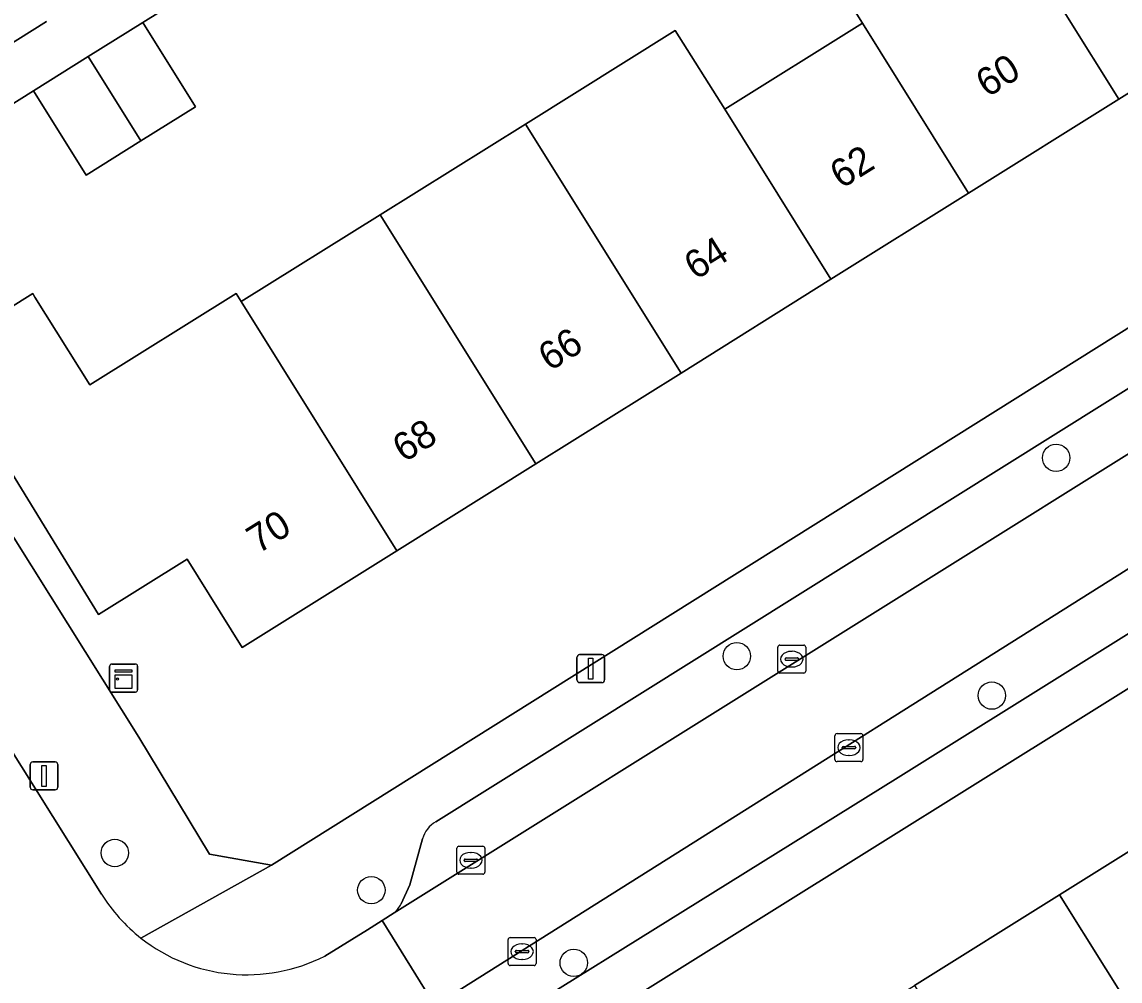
# Model space of a CAD drawing. Extents: x 159352 to 160617, y 385888 to 387323.
# Drawn here: x 159671.45 to 159710.67, y 386048.83 to 386083.08 of the extents above; entities that cross this region are included whole.
import ezdxf

# ---------------------------------------------------------------- set-up
doc = ezdxf.new("R2010")
doc.units = 0
for name, color, linetype in [('IMGEO_Boom', 7, 'Continuous'), ('IMGEO_Erf', 7, 'Continuous'), ('IMGEO_Kast', 7, 'Continuous'), ('IMGEO_Kolk', 7, 'Continuous'), ('IMGEO_Lichtmast', 7, 'Continuous'), ('IMGEO_Pand', 7, 'Continuous'), ('IMGEO_Pand_nummerreeks', 7, 'Continuous'), ('IMGEO_Parkeervlak_open', 7, 'Continuous'), ('IMGEO_Rijbaan_lokaal_open', 7, 'Continuous'), ('IMGEO_Voetpad_gesloten', 7, 'Continuous'), ('IMGEO_Voetpad_open', 7, 'Continuous')]:
    doc.layers.add(name, color=color, linetype=linetype)

msp = doc.modelspace()

# ---------------------------------------------------------------- linework, layer by layer
at = {"layer": 'IMGEO_Boom'}
for centre in [(159708.383, 386067.514), (159696.983, 386060.434), (159706.089, 386059.024), (159674.766, 386053.404), (159683.927, 386052.079), (159691.156, 386049.481)]:
    msp.add_circle(centre, 0.489, dxfattribs=at)
at = {"layer": 'IMGEO_Erf'}
for points in [[(159627.21, 386134.74), (159663.189, 386077.37), (159672.327, 386083.101)], [(159682.021, 386086.971), (159675.765, 386083.062), (159677.645, 386080.051), (159675.693, 386078.833), (159673.743, 386077.616), (159671.864, 386080.628), (159664.171, 386075.803), (159675.622, 386057.544), (159678.147, 386053.368), (159680.364, 386052.973), (159727.06, 386082.254), (159727.834, 386084.857)], [(159715.741, 386083.528), (159710.62, 386080.324), (159705.257, 386076.97), (159700.341, 386073.894), (159694.987, 386070.545), (159689.802, 386067.302), (159684.835, 386064.194), (159679.316, 386060.742), (159677.344, 386063.895), (159674.183, 386061.917), (159668.443, 386071.26), (159671.836, 386073.379), (159671.913, 386073.256), (159673.873, 386070.118), (159679.098, 386073.381), (159679.277, 386073.094), (159684.247, 386076.198), (159689.434, 386079.437), (159694.775, 386082.772), (159696.55, 386079.963), (159701.469, 386083.035), (159701.464, 386083.043), (159699.747, 386085.796)], [(159692.572, 386024.604), (159688.668, 386030.843), (159686.251, 386029.331), (159682.354, 386035.559), (159687.801, 386038.964), (159692.982, 386042.203), (159698.161, 386045.441), (159703.328, 386048.671), (159708.502, 386051.905), (159713.682, 386055.143)]]:
    msp.add_lwpolyline(points, dxfattribs=at)
msp.add_lwpolyline([(159733.186, 386035.211), (159730.405, 386039.383), (159739.998, 386045.377), (159726.053, 386067.427), (159724.652, 386067.823), (159682.76, 386041.661), (159677.195, 386038.177), (159676.499, 386035.726), (159692.861, 386009.756), (159693.588, 386010.224), (159695.905, 386011.714), (159692.99, 386016.431), (159699.422, 386020.406), (159702.337, 386015.688), (159707.722, 386019.015), (159705.988, 386021.823), (159710.701, 386024.734), (159712.435, 386021.927)], close=True, dxfattribs=at)
at = {"layer": 'IMGEO_Kast'}
for p, q in [((159674.58, 386059.227), (159674.58, 386060.068)), ((159674.58, 386060.068), (159674.58, 386059.227)), ((159674.655, 386060.152), (159675.496, 386060.152)), ((159675.496, 386060.152), (159674.655, 386060.152)), ((159675.58, 386060.077), (159675.58, 386059.236)), ((159675.58, 386059.236), (159675.58, 386060.077)), ((159675.505, 386059.152), (159674.664, 386059.152)), ((159674.664, 386059.152), (159675.505, 386059.152))]:
    msp.add_line(p, q, dxfattribs=at)
for points in [[(159674.775, 386059.942), (159675.375, 386059.942), (159675.375, 386059.857), (159674.775, 386059.857), (159674.775, 386059.942)], [(159674.775, 386059.767), (159675.375, 386059.767), (159675.375, 386059.278), (159674.775, 386059.278), (159674.775, 386059.767)]]:
    msp.add_lwpolyline(points, dxfattribs=at)
msp.add_circle((159674.859, 386059.616), 0.0377, dxfattribs=at)
for centre, start, end in [((159674.658, 386060.074), 92.4484, 184.2845), ((159674.658, 386060.074), 92.4484, 184.2845), ((159675.502, 386060.074), 2.4484, 94.2845), ((159675.502, 386060.074), 2.4484, 94.2845), ((159674.658, 386059.23), 182.4484, 274.2845), ((159674.658, 386059.23), 182.4484, 274.2845), ((159675.502, 386059.23), 272.4484, 4.2845), ((159675.502, 386059.23), 272.4484, 4.2845)]:
    msp.add_arc(centre, 0.0779, start, end, dxfattribs=at)
at = {"layer": 'IMGEO_Kolk'}
for p, q in [((159698.443, 386059.9), (159698.443, 386060.752)), ((159698.518, 386060.826), (159699.37, 386060.826)), ((159698.931, 386060.606), (159698.956, 386060.606)), ((159699.444, 386060.752), (159699.444, 386059.9)), ((159698.702, 386060.32), (159698.702, 386060.332)), ((159699.14, 386060.283), (159698.742, 386060.283)), ((159698.745, 386060.369), (159699.143, 386060.369)), ((159699.186, 386060.332), (159699.186, 386060.32)), ((159699.37, 386059.826), (159698.518, 386059.826)), ((159698.954, 386060.046), (159698.929, 386060.046)), ((159700.484, 386056.741), (159700.484, 386057.593)), ((159700.559, 386057.667), (159701.411, 386057.667)), ((159700.972, 386057.447), (159700.997, 386057.447)), ((159701.485, 386057.593), (159701.485, 386056.741)), ((159700.743, 386057.161), (159700.743, 386057.173)), ((159701.181, 386057.124), (159700.783, 386057.124)), ((159700.786, 386057.21), (159701.184, 386057.21)), ((159701.227, 386057.173), (159701.227, 386057.161)), ((159701.411, 386056.667), (159700.559, 386056.667)), ((159700.995, 386056.887), (159700.97, 386056.887)), ((159686.982, 386052.719), (159686.982, 386053.571)), ((159687.057, 386053.645), (159687.909, 386053.645)), ((159687.983, 386053.571), (159687.983, 386052.719)), ((159687.241, 386053.139), (159687.241, 386053.151)), ((159687.284, 386053.188), (159687.682, 386053.188)), ((159687.47, 386053.425), (159687.495, 386053.425)), ((159687.725, 386053.151), (159687.725, 386053.139)), ((159687.679, 386053.102), (159687.281, 386053.102)), ((159687.493, 386052.865), (159687.468, 386052.865)), ((159687.909, 386052.645), (159687.057, 386052.645)), ((159688.886, 386050.383), (159689.738, 386050.383)), ((159688.811, 386049.457), (159688.811, 386050.309)), ((159689.299, 386050.163), (159689.324, 386050.163)), ((159689.812, 386050.309), (159689.812, 386049.457)), ((159689.07, 386049.877), (159689.07, 386049.889)), ((159689.508, 386049.84), (159689.11, 386049.84)), ((159689.113, 386049.926), (159689.511, 386049.926)), ((159689.322, 386049.603), (159689.297, 386049.603)), ((159689.554, 386049.889), (159689.554, 386049.877)), ((159689.738, 386049.383), (159688.886, 386049.383))]:
    msp.add_line(p, q, dxfattribs=at)
for points in [[(159698.443, 386059.9), (159698.443, 386060.752)], [(159698.518, 386060.826), (159699.37, 386060.826)], [(159699.444, 386060.752), (159699.444, 386059.9)], [(159699.37, 386059.826), (159698.518, 386059.826)], [(159700.484, 386056.741), (159700.484, 386057.593)], [(159700.559, 386057.667), (159701.411, 386057.667)], [(159701.485, 386057.593), (159701.485, 386056.741)], [(159701.411, 386056.667), (159700.559, 386056.667)], [(159686.982, 386052.719), (159686.982, 386053.571)], [(159687.057, 386053.645), (159687.909, 386053.645)], [(159687.983, 386053.571), (159687.983, 386052.719)], [(159687.909, 386052.645), (159687.057, 386052.645)], [(159688.886, 386050.383), (159689.738, 386050.383)], [(159688.811, 386049.457), (159688.811, 386050.309)], [(159689.812, 386050.309), (159689.812, 386049.457)], [(159689.738, 386049.383), (159688.886, 386049.383)]]:
    msp.add_lwpolyline(points, dxfattribs=at)
for centre, radius, start, end in [((159698.52, 386060.75), 0.0765, 91.552, 178.448), ((159698.52, 386060.75), 0.0765, 91.552, 178.448), ((159699.368, 386060.75), 0.0765, 1.552, 88.448), ((159699.368, 386060.75), 0.0765, 1.552, 88.448), ((159698.742, 386060.329), 0.0403, 85.8775, 175.7526), ((159698.739, 386060.319), 0.0366, 178.938, 274.7102), ((159699.143, 386060.326), 0.043, 264.8664, 352.4533), ((159699.147, 386060.331), 0.0386, 1.7309, 96.639), ((159698.52, 386059.902), 0.0765, 181.552, 268.448), ((159698.52, 386059.902), 0.0765, 181.552, 268.448), ((159699.368, 386059.902), 0.0765, 271.552, 358.448), ((159699.368, 386059.902), 0.0765, 271.552, 358.448), ((159700.561, 386057.591), 0.0765, 91.552, 178.448), ((159700.561, 386057.591), 0.0765, 91.552, 178.448), ((159701.409, 386057.591), 0.0765, 1.552, 88.448), ((159701.409, 386057.591), 0.0765, 1.552, 88.448), ((159700.783, 386057.17), 0.0403, 85.8775, 175.7526), ((159700.78, 386057.16), 0.0366, 178.938, 274.7102), ((159701.184, 386057.167), 0.043, 264.8664, 352.4533), ((159701.188, 386057.172), 0.0386, 1.7309, 96.639), ((159700.561, 386056.743), 0.0765, 181.552, 268.448), ((159700.561, 386056.743), 0.0765, 181.552, 268.448), ((159701.409, 386056.743), 0.0765, 271.552, 358.448), ((159701.409, 386056.743), 0.0765, 271.552, 358.448), ((159687.059, 386053.569), 0.0765, 91.552, 178.448), ((159687.059, 386053.569), 0.0765, 91.552, 178.448), ((159687.907, 386053.569), 0.0765, 1.552, 88.448), ((159687.907, 386053.569), 0.0765, 1.552, 88.448), ((159687.281, 386053.148), 0.0403, 85.8775, 175.7526), ((159687.278, 386053.138), 0.0366, 178.938, 274.7102), ((159687.682, 386053.145), 0.043, 264.8664, 352.4533), ((159687.686, 386053.15), 0.0386, 1.7309, 96.639), ((159687.059, 386052.721), 0.0765, 181.552, 268.448), ((159687.059, 386052.721), 0.0765, 181.552, 268.448), ((159687.907, 386052.721), 0.0765, 271.552, 358.448), ((159687.907, 386052.721), 0.0765, 271.552, 358.448), ((159688.888, 386050.307), 0.0765, 91.552, 178.448), ((159688.888, 386050.307), 0.0765, 91.552, 178.448), ((159689.736, 386050.307), 0.0765, 1.552, 88.448), ((159689.736, 386050.307), 0.0765, 1.552, 88.448), ((159689.11, 386049.886), 0.0403, 85.8775, 175.7526), ((159689.107, 386049.876), 0.0366, 178.938, 274.7102), ((159689.511, 386049.883), 0.043, 264.8664, 352.4533), ((159689.515, 386049.888), 0.0386, 1.7309, 96.639), ((159688.888, 386049.459), 0.0765, 181.552, 268.448), ((159688.888, 386049.459), 0.0765, 181.552, 268.448), ((159689.736, 386049.459), 0.0765, 271.552, 358.448), ((159689.736, 386049.459), 0.0765, 271.552, 358.448)]:
    msp.add_arc(centre, radius, start, end, dxfattribs=at)
for centre, major_axis, ratio, start_param, end_param in [((159698.93, 386060.326), (-0.387, 0.002), 0.722429, 4.712389, 7.853982), ((159698.955, 386060.326), (-0.39, 0.002), 0.717154, 1.570796, 4.712389), ((159700.971, 386057.167), (-0.387, 0.002), 0.722429, 4.712389, 7.853982), ((159700.996, 386057.167), (-0.39, 0.002), 0.717154, 1.570796, 4.712389), ((159687.469, 386053.145), (-0.387, 0.002), 0.722429, 4.712389, 7.853982), ((159687.494, 386053.145), (-0.39, 0.002), 0.717154, 1.570796, 4.712389), ((159689.298, 386049.883), (-0.387, 0.002), 0.722429, 4.712389, 7.853982), ((159689.323, 386049.883), (-0.39, 0.002), 0.717154, 1.570796, 4.712389)]:
    msp.add_ellipse(centre, major_axis=major_axis, ratio=ratio, start_param=start_param, end_param=end_param, dxfattribs=at)
at = {"layer": 'IMGEO_Lichtmast'}
for p, q in [((159691.267, 386059.587), (159691.267, 386060.387)), ((159691.267, 386060.387), (159691.267, 386059.587)), ((159691.367, 386060.487), (159692.157, 386060.487)), ((159692.157, 386060.487), (159691.367, 386060.487)), ((159692.257, 386060.387), (159692.257, 386059.587)), ((159692.257, 386059.587), (159692.257, 386060.387)), ((159692.157, 386059.487), (159691.367, 386059.487)), ((159691.367, 386059.487), (159692.157, 386059.487)), ((159671.842, 386056.659), (159672.632, 386056.659)), ((159672.632, 386056.659), (159671.842, 386056.659)), ((159671.742, 386055.759), (159671.742, 386056.559)), ((159671.742, 386056.559), (159671.742, 386055.759)), ((159672.732, 386056.559), (159672.732, 386055.759)), ((159672.732, 386055.759), (159672.732, 386056.559)), ((159672.632, 386055.659), (159671.842, 386055.659)), ((159671.842, 386055.659), (159672.632, 386055.659))]:
    msp.add_line(p, q, dxfattribs=at)
for points in [[(159691.687, 386060.362), (159691.837, 386060.362), (159691.837, 386059.612), (159691.687, 386059.612), (159691.687, 386060.362)], [(159672.162, 386056.534), (159672.312, 386056.534), (159672.312, 386055.784), (159672.162, 386055.784), (159672.162, 386056.534)]]:
    msp.add_lwpolyline(points, dxfattribs=at)
for centre, start, end in [((159691.367, 386060.387), 90, 180), ((159691.367, 386060.387), 90, 180), ((159692.157, 386060.387), 0, 90), ((159692.157, 386060.387), 360, 90), ((159691.367, 386059.587), 180, 270), ((159691.367, 386059.587), 180, 270), ((159692.157, 386059.587), 270, 0), ((159692.157, 386059.587), 270, 0), ((159671.842, 386056.559), 90, 180), ((159671.842, 386056.559), 90, 180), ((159672.632, 386056.559), 0, 90), ((159672.632, 386056.559), 360, 90), ((159671.842, 386055.759), 180, 270), ((159671.842, 386055.759), 180, 270), ((159672.632, 386055.759), 270, 0), ((159672.632, 386055.759), 270, 0)]:
    msp.add_arc(centre, 0.1, start, end, dxfattribs=at)
at = {"layer": 'IMGEO_Pand'}
for points in [[(159710.256, 386092.311), (159705.178, 386089.14), (159705.249, 386089.026), (159706.834, 386086.386), (159710.62, 386080.324), (159715.741, 386083.528)], [(159706.834, 386086.386), (159705.249, 386089.026), (159705.178, 386089.14), (159699.712, 386085.853), (159699.747, 386085.796), (159701.464, 386083.043), (159701.469, 386083.035), (159705.257, 386076.97), (159710.62, 386080.324)], [(159675.693, 386078.833), (159677.645, 386080.051), (159675.765, 386083.062), (159673.813, 386081.844)], [(159700.341, 386073.894), (159705.257, 386076.97), (159701.469, 386083.035), (159696.55, 386079.963)], [(159696.55, 386079.963), (159694.775, 386082.772), (159689.434, 386079.437), (159694.987, 386070.545), (159700.341, 386073.894)], [(159673.813, 386081.844), (159671.864, 386080.628), (159673.743, 386077.616), (159675.693, 386078.833)], [(159689.802, 386067.302), (159694.987, 386070.545), (159689.434, 386079.437), (159684.247, 386076.198)], [(159679.277, 386073.094), (159684.835, 386064.194), (159689.802, 386067.302), (159684.247, 386076.198)], [(159679.098, 386073.381), (159673.873, 386070.118), (159671.913, 386073.256), (159671.836, 386073.379), (159668.443, 386071.26), (159674.183, 386061.917), (159677.344, 386063.895), (159679.316, 386060.742), (159684.835, 386064.194), (159679.277, 386073.094)], [(159713.682, 386055.143), (159708.502, 386051.905), (159713.466, 386043.98), (159713.984, 386043.152), (159713.74, 386042.999), (159715.63, 386039.982), (159717.73, 386041.298), (159715.841, 386044.315), (159719.171, 386046.4)], [(159708.502, 386051.905), (159703.328, 386048.671), (159707.246, 386042.417), (159708.294, 386040.745), (159711.6, 386042.813), (159715.372, 386036.791), (159716.992, 386037.806), (159715.63, 386039.982), (159713.74, 386042.999), (159713.984, 386043.152), (159713.466, 386043.98)]]:
    msp.add_lwpolyline(points, close=True, dxfattribs=at)
at = {"layer": 'IMGEO_Parkeervlak_open'}
for points in [[(159684.747, 386051.268), (159715.668, 386070.601)], [(159712.06, 386070.688), (159686.23, 386054.518)], [(159717.543, 386067.695), (159686.194, 386047.956), (159678.382, 386043.037)], [(159681.467, 386042.865), (159702.746, 386056.105), (159715.811, 386064.272)], [(159685.758, 386053.909), (159685.302, 386052.262), (159684.993, 386051.59)]]:
    msp.add_lwpolyline(points, dxfattribs=at)
for centre, radius, start, end in [((159686.728, 386053.644), 1.006, 119.703, 164.7427), ((159684.062, 386052.046), 1.036, 311.3464, 333.8958)]:
    msp.add_arc(centre, radius, start, end, dxfattribs=at)
at = {"layer": 'IMGEO_Rijbaan_lokaal_open'}
msp.add_lwpolyline([(159684.747, 386051.268), (159684.308, 386050.988), (159686.194, 386047.956), (159717.543, 386067.695), (159717.747, 386067.827), (159715.89, 386070.74), (159715.668, 386070.601)], close=True, dxfattribs=at)
for points in [[(159674.287, 386051.938), (159670.239, 386058.378), (159666.118, 386055.802), (159666.336, 386055.453), (159670.019, 386049.55)], [(159678.382, 386043.037), (159686.194, 386047.956), (159684.308, 386050.988), (159683.792, 386050.662), (159682.262, 386049.724)]]:
    msp.add_lwpolyline(points, dxfattribs=at)
for centre, radius, start, end in [((159679.492, 386055.19), 6.137, 211.9967, 231.8286), ((159679.482, 386055.181), 6.125, 231.8513, 296.9921)]:
    msp.add_arc(centre, radius, start, end, dxfattribs=at)
at = {"layer": 'IMGEO_Voetpad_gesloten'}
msp.add_lwpolyline([(159672.327, 386083.101), (159663.189, 386077.37), (159664.171, 386075.803), (159671.864, 386080.628), (159673.813, 386081.844), (159675.765, 386083.062), (159682.021, 386086.971)], dxfattribs=at)
at = {"layer": 'IMGEO_Voetpad_open'}
for points in [[(159675.699, 386050.365), (159680.364, 386052.973), (159678.147, 386053.368), (159675.622, 386057.544), (159664.171, 386075.803), (159663.189, 386077.37), (159627.21, 386134.74)], [(159731.503, 386085.122), (159727.06, 386082.254), (159680.364, 386052.973), (159675.699, 386050.365)], [(159686.23, 386054.518), (159712.06, 386070.688)], [(159674.294, 386034.404), (159676.499, 386035.726), (159677.195, 386038.177), (159682.76, 386041.661), (159724.652, 386067.823)], [(159715.811, 386064.272), (159702.746, 386056.105), (159681.467, 386042.865)], [(159670.239, 386058.378), (159674.287, 386051.938)], [(159684.993, 386051.59), (159685.302, 386052.262), (159685.758, 386053.909)], [(159682.262, 386049.724), (159683.792, 386050.662), (159684.308, 386050.988), (159684.747, 386051.268)]]:
    msp.add_lwpolyline(points, dxfattribs=at)
for centre, radius, start, end in [((159686.728, 386053.644), 1.006, 119.703, 164.7427), ((159679.492, 386055.19), 6.137, 211.9967, 231.8286), ((159684.062, 386052.046), 1.036, 311.3464, 333.8958), ((159679.482, 386055.181), 6.125, 231.8513, 296.9921)]:
    msp.add_arc(centre, radius, start, end, dxfattribs=at)

# ---------------------------------------------------------------- texts
at = {"layer": 'IMGEO_Pand_nummerreeks'}
for s, rotation, p in [('60', 32.0283, (159705.929, 386080.362)), ('62', 32.028, (159700.716, 386077.101)), ('64', 32.028, (159695.509, 386073.844)), ('66', 32.028, (159690.301, 386070.586)), ('68', 32.028, (159685.095, 386067.329)), ('70', 32.028, (159679.886, 386064.071))]:
    msp.add_text(s, height=1, rotation=rotation, dxfattribs=at).set_placement(p)

doc.saveas('drawing.dxf')
